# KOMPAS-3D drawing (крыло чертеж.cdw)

Views: Проекционный вид 2, Вид по стрелке 8, Разрез Г-Г, Проекционный вид 10, Вид по стрелке 13
Referenced files in D:\Andrew\Aviamodels\Крыло\: Крыло Сборка.a3d
Referenced files: крыло чертеж.cdw
Referenced files in C:\Andrew\aviamodels\Крыло\: Трубка.m3d, Крыло.m3d, Элерон.m3d, Законцовка.m3d, Крыло Сборка.a3d
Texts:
  Сборка
  X-ТEAM Group
  Трубка
  Крыло левое
  Элерон
  Законцовка
Dimensions and other numbers on the sheet: 265; 132,5; 493,76; 445,64; 39,91; 198,62; 1:1; 1; 17,76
